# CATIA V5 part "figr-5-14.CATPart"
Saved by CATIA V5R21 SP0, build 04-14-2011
Part number: Part1
Bounding box of the stored display mesh (mm): x 0 to 150, y -70 to 70, z -150 to 69.804
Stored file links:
  D:\CATIA V5R21 E-RESOURCES\CATIA-V5R21\catia-v5r21-prt\c05-catia-v5r20-prt\catia-v5r21-figr-5-14.CATPart
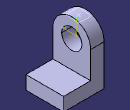
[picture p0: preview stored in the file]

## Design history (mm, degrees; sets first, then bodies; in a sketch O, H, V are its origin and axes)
Set1
  Plane1: type Offset, RefPlane face of Pad1, Offset -18, reversed
  Plane2: type Tangent, Support face of Pad1, RefPoint Sketch3
Body1 (main body)
  Sketch1 on yz-plane, origin (0, 0, 0), H (0, 1, 0), V (0, 0, 1)
    arc A1 centre (0, 0) radius 70 from (70, 0) to (-70, 0) ccw
    point P1 (70, 0)
    point P2 (-70, 0)
    line L1 (-70, 0) -> (-70, -150)
    line L2 (-70, -150) -> (70, -150)
    line L3 (70, -150) -> (70, 0)
    circle A2 centre (0, 0) radius 37.5
    radius A1 = 70
    radius A2 = 37.5
    distance O L2 = 150
    coincidence: P1 H, P2 H
    tangency: L1 A1, L3 A1
    horizontal: L2 H
  Pad1: profile Sketch1, direction (1, 0, 0), length 50
  Sketch2 on face of Pad1, origin (50, 0, 0), H (0, 1, 0), V (0, 0, 1)
    line L1 (-70, -150) -> (70, -150)
    line L2 (70, -150) -> (70, -100)
    line L3 (70, -100) -> (-70, -100)
    line L4 (-70, -100) -> (-70, -150)
    reference projected line E1 (-70, -150) -> (70, -150) from edge [face of Pad1 | face of Pad1]
    reference projected line E2 (-70, 0) -> (-70, -150) from edge [face of Pad1 | face of Pad1]
    reference projected line E3 (70, -150) -> (70, 0) from edge [face of Pad1 | face of Pad1]
    length L2 = 50
    horizontal: L1 H, L3 H
    vertical: L2 V, L4 V
    coincidence: L1 E1, E2 L4, L2 E3
  Pad2: profile Sketch2, direction (1, 0, 0), length 100
  Sketch3 on Plane1, origin (32, 0, 0), H (0, -1, 0), V (0, 0, 1)
    point P1 (-7.2142, 69.6273)
    reference projected arc E1 centre (0, 0) radius 70 from (70, 0) to (-70, 0) ccw from edge [face of Pad1 | face of Pad1]
    coincidence: P1 E1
